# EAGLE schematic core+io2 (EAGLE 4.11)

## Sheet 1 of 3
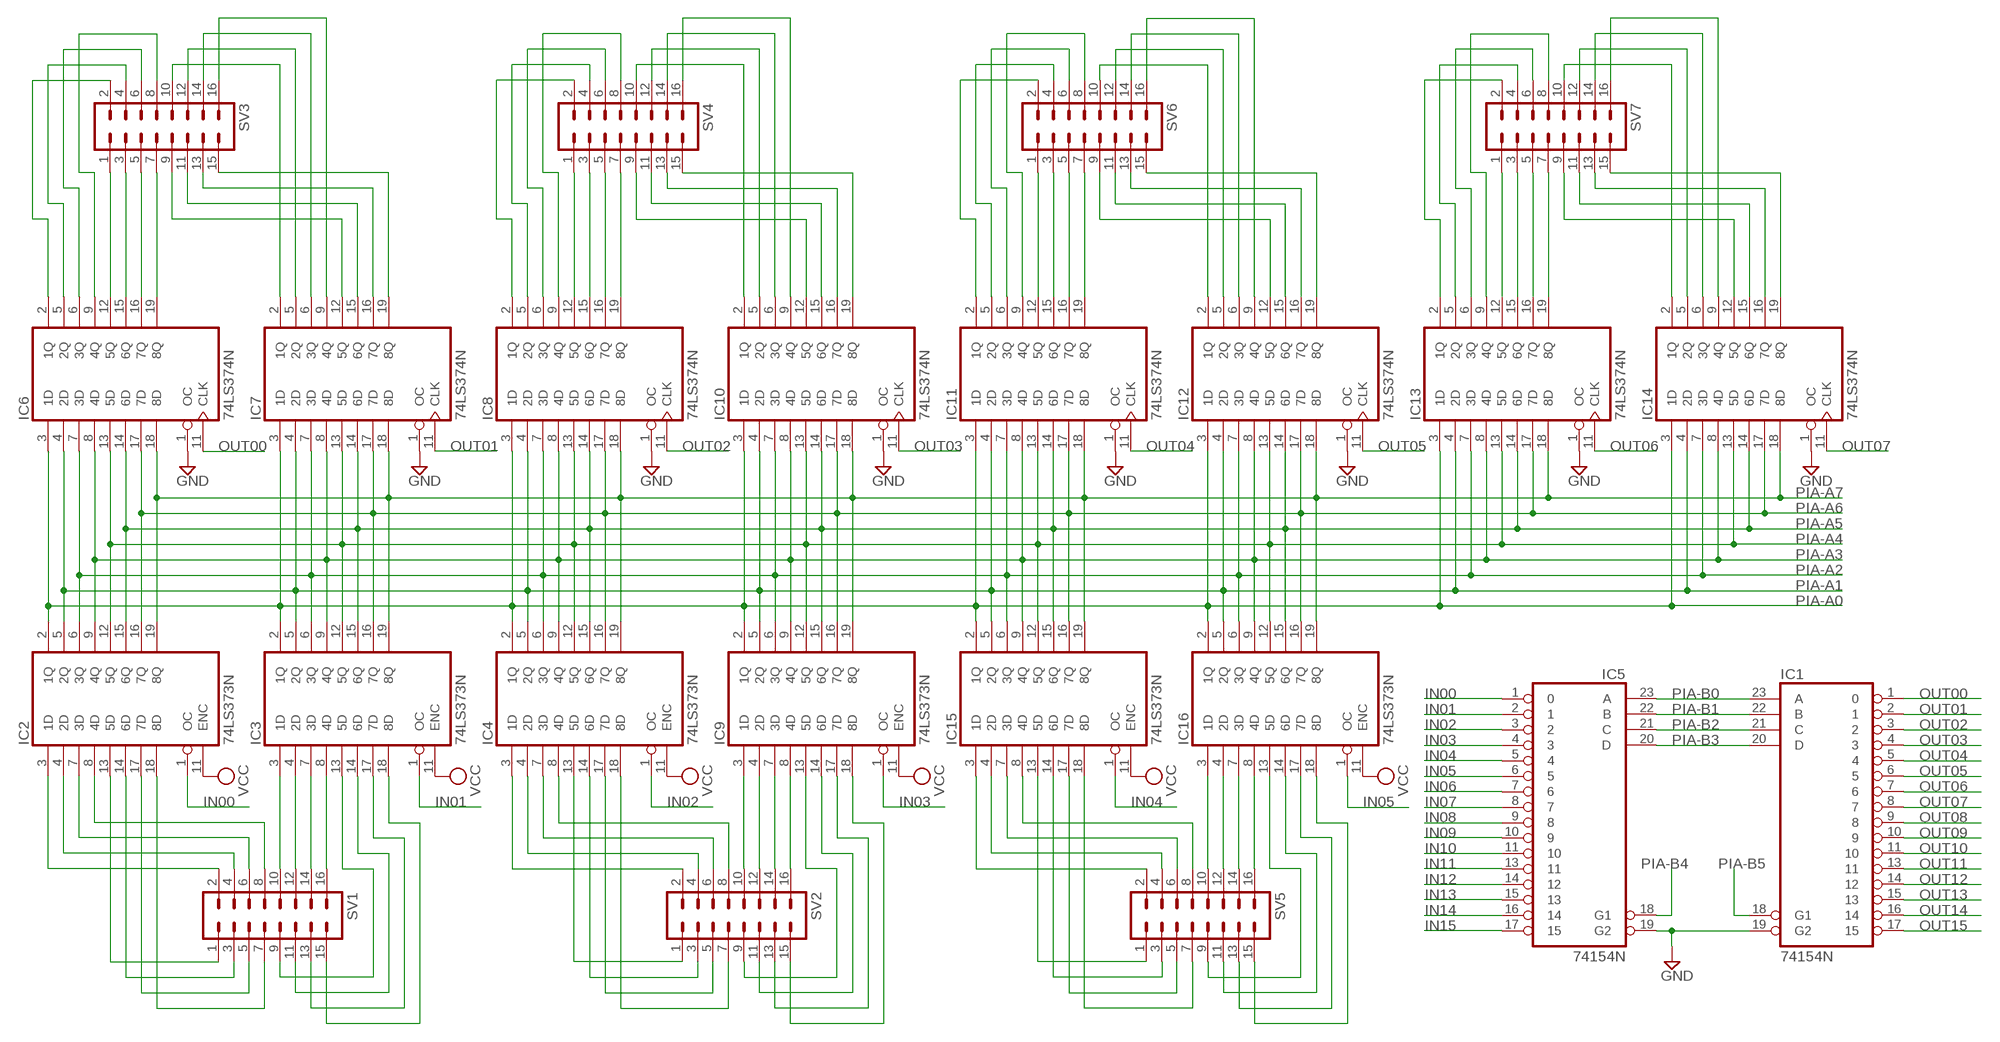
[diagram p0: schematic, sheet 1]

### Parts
IC1  74154N  [DIL24-6]
IC2  74LS373N  [DIL20]
IC3  74LS373N  [DIL20]
IC4  74LS373N  [DIL20]
IC5  74154N  [DIL24-6]
IC6  74LS374N  [DIL20]
IC7  74LS374N  [DIL20]
IC8  74LS374N  [DIL20]
IC9  74LS373N  [DIL20]
IC10  74LS374N  [DIL20]
IC11  74LS374N  [DIL20]
IC12  74LS374N  [DIL20]
IC13  74LS374N  [DIL20]
IC14  74LS374N  [DIL20]
IC15  74LS373N  [DIL20]
IC16  74LS373N  [DIL20]
SV1  MA08-2  [MA08-2]
SV2  MA08-2  [MA08-2]
SV3  MA08-2  [MA08-2]
SV4  MA08-2  [MA08-2]
SV5  MA08-2  [MA08-2]
SV6  MA08-2  [MA08-2]
SV7  MA08-2  [MA08-2]

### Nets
GND [Power]: IC1.19(G2) IC5.19(G2) IC6.1(OC) IC7.1(OC) IC8.1(OC) IC10.1(OC) IC11.1(OC) IC12.1(OC) IC13.1(OC) IC14.1(OC) ; also sheet 2,3
IN00: IC2.1(OC) IC5.1
IN01: IC3.1(OC) IC5.2
IN02: IC4.1(OC) IC5.3
IN03: IC5.4 IC9.1(OC)
IN04: IC5.5 IC15.1(OC)
IN05: IC5.6 IC16.1(OC)
IN06: IC5.7
IN07: IC5.8
IN08: IC5.9
IN09: IC5.10
IN10: IC5.11
IN11: IC5.13
IN12: IC5.14
IN13: IC5.15
IN14: IC5.16
IN15: IC5.17
N$1: IC3.3(1D) SV1.10
N$2: IC3.4(2D) SV1.12
N$7: IC3.7(3D) SV1.14
N$8: IC3.8(4D) SV1.16
N$9: IC2.8(4D) SV1.8
N$10: IC2.7(3D) SV1.6
N$11: IC2.4(2D) SV1.4
N$12: IC2.3(1D) SV1.2
N$13: IC2.13(5D) SV1.1
N$14: IC2.14(6D) SV1.3
N$15: IC2.17(7D) SV1.5
N$16: IC2.18(8D) SV1.7
N$17: IC3.13(5D) SV1.9
N$18: IC3.14(6D) SV1.11
N$19: IC3.17(7D) SV1.13
N$20: IC3.18(8D) SV1.15
N$26: IC11.2(1Q) IC13.2(1Q) SV6.2 SV7.2
N$29: IC9.3(1D) SV2.10
N$30: IC9.4(2D) SV2.12
N$31: IC9.7(3D) SV2.14
N$32: IC9.8(4D) SV2.16
N$33: IC8.12(5Q) SV4.1
N$34: IC8.15(6Q) SV4.3
N$35: IC8.16(7Q) SV4.5
N$36: IC8.19(8Q) SV4.7
N$37: IC4.3(1D) SV2.2
N$38: IC4.4(2D) SV2.4
N$39: IC4.7(3D) SV2.6
N$40: IC4.8(4D) SV2.8
N$41: IC9.13(5D) SV2.9
N$42: IC9.14(6D) SV2.11
N$43: IC9.17(7D) SV2.13
N$44: IC9.18(8D) SV2.15
N$45: IC4.13(5D) SV2.1
N$46: IC4.14(6D) SV2.3
N$47: IC4.17(7D) SV2.5
N$48: IC4.18(8D) SV2.7
N$49: IC8.5(2Q) SV4.4
N$50: IC8.6(3Q) SV4.6
N$51: IC8.2(1Q) SV4.2
N$52: IC8.9(4Q) SV4.8
N$53: IC6.12(5Q) SV3.1
N$54: IC6.15(6Q) SV3.3
N$55: IC6.16(7Q) SV3.5
N$56: IC6.19(8Q) SV3.7
N$57: IC6.2(1Q) SV3.2
N$58: IC6.5(2Q) SV3.4
N$59: IC6.6(3Q) SV3.6
N$60: IC6.9(4Q) SV3.8
N$61: IC7.19(8Q) SV3.15
N$62: IC7.16(7Q) SV3.13
N$63: IC7.15(6Q) SV3.11
N$64: IC7.12(5Q) SV3.9
N$65: IC7.2(1Q) SV3.10
N$66: IC7.5(2Q) SV3.12
N$67: IC7.6(3Q) SV3.14
N$68: IC7.9(4Q) SV3.16
N$69: IC10.2(1Q) SV4.10
N$70: IC10.5(2Q) SV4.12
N$71: IC10.6(3Q) SV4.14
N$72: IC10.9(4Q) SV4.16
N$73: IC10.19(8Q) SV4.15
N$74: IC10.16(7Q) SV4.13
N$75: IC10.15(6Q) SV4.11
N$76: IC10.12(5Q) SV4.9
N$77: IC16.3(1D) SV5.10
N$78: IC16.4(2D) SV5.12
N$79: IC16.7(3D) SV5.14
N$80: IC16.8(4D) SV5.16
N$81: IC11.12(5Q) SV6.1
N$82: IC11.15(6Q) SV6.3
N$83: IC11.16(7Q) SV6.5
N$84: IC11.19(8Q) SV6.7
N$85: IC13.12(5Q) SV7.1
N$86: IC13.15(6Q) SV7.3
N$87: IC13.16(7Q) SV7.5
N$88: IC13.19(8Q) SV7.7
N$89: IC11.5(2Q) SV6.4
N$90: IC11.6(3Q) SV6.6
N$91: IC11.9(4Q) SV6.8
N$92: IC12.12(5Q) SV6.9
N$93: IC12.15(6Q) SV6.11
N$95: IC12.16(7Q) SV6.13
N$96: IC12.19(8Q) SV6.15
N$97: IC12.2(1Q) SV6.10
N$98: IC12.5(2Q) SV6.12
N$99: IC12.6(3Q) SV6.14
N$100: IC12.9(4Q) SV6.16
N$101: IC15.3(1D) SV5.2
N$102: IC15.4(2D) SV5.4
N$103: IC15.7(3D) SV5.6
N$104: IC15.8(4D) SV5.8
N$105: IC16.13(5D) SV5.9
N$106: IC16.14(6D) SV5.11
N$107: IC16.17(7D) SV5.13
N$108: IC16.18(8D) SV5.15
N$109: IC15.13(5D) SV5.1
N$110: IC15.14(6D) SV5.3
N$111: IC15.17(7D) SV5.5
N$112: IC15.18(8D) SV5.7
N$113: IC14.19(8Q) SV7.15
N$114: IC14.16(7Q) SV7.13
N$115: IC14.15(6Q) SV7.11
N$116: IC14.12(5Q) SV7.9
N$117: IC14.2(1Q) SV7.10
N$118: IC14.5(2Q) SV7.12
N$119: IC14.6(3Q) SV7.14
N$120: IC14.9(4Q) SV7.16
N$121: IC13.9(4Q) SV7.8
N$122: IC13.6(3Q) SV7.6
N$123: IC13.5(2Q) SV7.4
OUT00: IC1.1 IC6.11(CLK)
OUT01: IC1.2 IC7.11(CLK)
OUT02: IC1.3 IC8.11(CLK)
OUT03: IC1.4 IC10.11(CLK)
OUT04: IC1.5 IC11.11(CLK)
OUT05: IC1.6 IC12.11(CLK)
OUT06: IC1.7 IC13.11(CLK)
OUT07: IC1.8 IC14.11(CLK)
OUT08: IC1.9
OUT09: IC1.10
OUT10: IC1.11
OUT11: IC1.13
OUT12: IC1.14
OUT13: IC1.15
OUT14: IC1.16
OUT15: IC1.17
PIA-A0: IC2.2(1Q) IC3.2(1Q) IC4.2(1Q) IC6.3(1D) IC7.3(1D) IC8.3(1D) IC9.2(1Q) IC10.3(1D) IC11.3(1D) IC12.3(1D) IC13.3(1D) IC14.3(1D) IC15.2(1Q) IC16.2(1Q) ; also sheet 2,3
PIA-A1: IC2.5(2Q) IC3.5(2Q) IC4.5(2Q) IC6.4(2D) IC7.4(2D) IC8.4(2D) IC9.5(2Q) IC10.4(2D) IC11.4(2D) IC12.4(2D) IC13.4(2D) IC14.4(2D) IC15.5(2Q) IC16.5(2Q) ; also sheet 2,3
PIA-A2: IC2.6(3Q) IC3.6(3Q) IC4.6(3Q) IC6.7(3D) IC7.7(3D) IC8.7(3D) IC9.6(3Q) IC10.7(3D) IC11.7(3D) IC12.7(3D) IC13.7(3D) IC14.7(3D) IC15.6(3Q) IC16.6(3Q) ; also sheet 2,3
PIA-A3: IC2.9(4Q) IC3.9(4Q) IC4.9(4Q) IC6.8(4D) IC7.8(4D) IC8.8(4D) IC9.9(4Q) IC10.8(4D) IC11.8(4D) IC12.8(4D) IC13.8(4D) IC14.8(4D) IC15.9(4Q) IC16.9(4Q) ; also sheet 2,3
PIA-A4: IC2.12(5Q) IC3.12(5Q) IC4.12(5Q) IC6.13(5D) IC7.13(5D) IC8.13(5D) IC9.12(5Q) IC10.13(5D) IC11.13(5D) IC12.13(5D) IC13.13(5D) IC14.13(5D) IC15.12(5Q) IC16.12(5Q) ; also sheet 2,3
PIA-A5: IC2.15(6Q) IC3.15(6Q) IC4.15(6Q) IC6.14(6D) IC7.14(6D) IC8.14(6D) IC9.15(6Q) IC10.14(6D) IC11.14(6D) IC12.14(6D) IC13.14(6D) IC14.14(6D) IC15.15(6Q) IC16.15(6Q) ; also sheet 2,3
PIA-A6: IC2.16(7Q) IC3.16(7Q) IC4.16(7Q) IC6.17(7D) IC7.17(7D) IC8.17(7D) IC9.16(7Q) IC10.17(7D) IC11.17(7D) IC12.17(7D) IC13.17(7D) IC14.17(7D) IC15.16(7Q) IC16.16(7Q) ; also sheet 2,3
PIA-A7: IC2.19(8Q) IC3.19(8Q) IC4.19(8Q) IC6.18(8D) IC7.18(8D) IC8.18(8D) IC9.19(8Q) IC10.18(8D) IC11.18(8D) IC12.18(8D) IC13.18(8D) IC14.18(8D) IC15.19(8Q) IC16.19(8Q) ; also sheet 2,3
PIA-B0: IC1.23(A) IC5.23(A) ; also sheet 2,3
PIA-B1: IC1.22(B) IC5.22(B) ; also sheet 2,3
PIA-B2: IC1.21(C) IC5.21(C) ; also sheet 2,3
PIA-B3: IC1.20(D) IC5.20(D) ; also sheet 2,3
PIA-B4: IC5.18(G1) ; also sheet 2,3
PIA-B5: IC1.18(G1) ; also sheet 2,3
VCC [Power]: IC2.11(ENC) IC3.11(ENC) IC4.11(ENC) IC9.11(ENC) IC15.11(ENC) IC16.11(ENC) ; also sheet 2,3

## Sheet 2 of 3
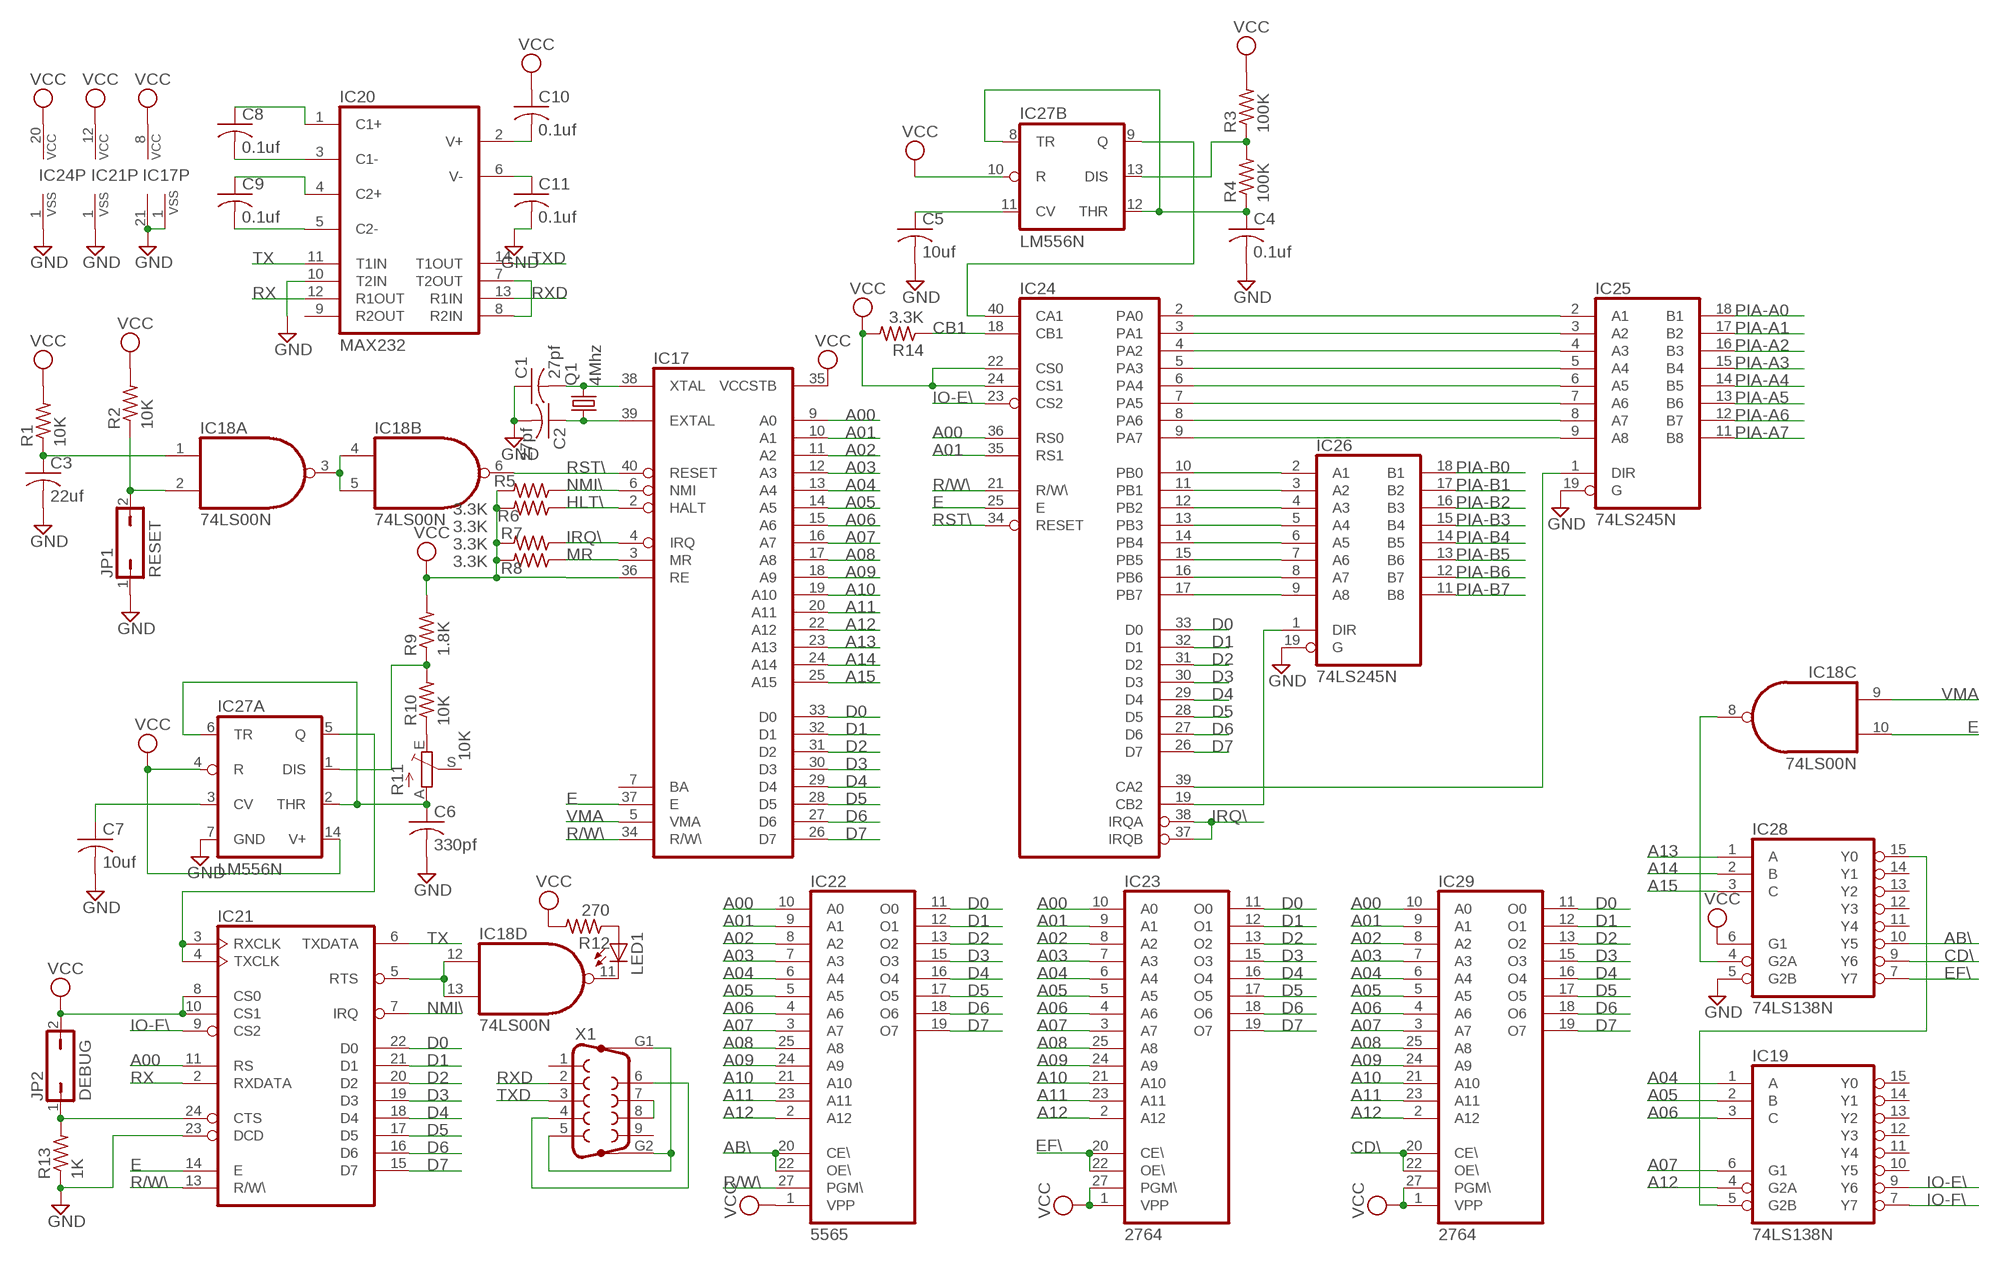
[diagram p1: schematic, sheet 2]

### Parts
C1  27pf  C-US050-025X075  [C050-025X075]
C2  27pf  C-US050-025X075  [C050-025X075]
C3  22uf  C-US050-025X075  [C050-025X075]
C4  0.1uf  C-US050-025X075  [C050-025X075]
C5  10uf  C-US050-025X075  [C050-025X075]
C6  330pf  C-US050-025X075  [C050-025X075]
C7  10uf  C-US050-025X075  [C050-025X075]
C8  0.1uf  C-US050-025X075  [C050-025X075]
C9  0.1uf  C-US050-025X075  [C050-025X075]
C10  0.1uf  C-US050-025X075  [C050-025X075]
C11  0.1uf  C-US050-025X075  [C050-025X075]
IC17  6802  [DIL40]
IC18  74LS00N  [DIL14]
IC19  74LS138N  [DIL16]
IC20  MAX232  [DIL16]
IC21  6850  [DIL24]
IC22  5565  2764  [DIL28]
IC23  2764  [DIL28]
IC24  6821  [DIL40]
IC25  74LS245N  [DIL20]
IC26  74LS245N  [DIL20]
IC27  LM556N  [DIL14]
IC28  74LS138N  [DIL16]
IC29  2764  [DIL28]
JP1  RESET  JP1Q  [JP1]
JP2  DEBUG  JP1Q  [JP1]
LED1  LED3MM  [LED3MM]
Q1  4Mhz  CRYTALHC18U-V  [HC18U-V]
R1  10K  R-US_0207/7  [0207/7]
R2  10K  R-US_0207/7  [0207/7]
R3  100K  R-US_0207/7  [0207/7]
R4  100K  R-US_0207/7  [0207/7]
R5  3.3K  R-US_0207/7  [0207/7]
R6  3.3K  R-US_0207/7  [0207/7]
R7  3.3K  R-US_0207/7  [0207/7]
R8  3.3K  R-US_0207/7  [0207/7]
R9  1.8K  R-US_0207/7  [0207/7]
R10  10K  R-US_0207/7  [0207/7]
R11  10K  TRIM_EU-B90P  [SP19L]
R12  270  R-US_0207/7  [0207/7]
R13  1K  R-US_0207/7  [0207/7]
R14  3.3K  R-US_0207/7  [0207/7]
X1  F09HP  [F09HP]

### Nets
A00: IC17.9(A0) IC21.11(RS) IC22.10(A0) IC23.10(A0) IC24.36(RS0) IC29.10(A0)
A01: IC17.10(A1) IC22.9(A1) IC23.9(A1) IC24.35(RS1) IC29.9(A1)
A02: IC17.11(A2) IC22.8(A2) IC23.8(A2) IC29.8(A2)
A03: IC17.12(A3) IC22.7(A3) IC23.7(A3) IC29.7(A3)
A04: IC17.13(A4) IC19.1(A) IC22.6(A4) IC23.6(A4) IC29.6(A4)
A05: IC17.14(A5) IC19.2(B) IC22.5(A5) IC23.5(A5) IC29.5(A5)
A06: IC17.15(A6) IC19.3(C) IC22.4(A6) IC23.4(A6) IC29.4(A6)
A07: IC17.16(A7) IC19.6(G1) IC22.3(A7) IC23.3(A7) IC29.3(A7)
A08: IC17.17(A8) IC22.25(A8) IC23.25(A8) IC29.25(A8)
A09: IC17.18(A9) IC22.24(A9) IC23.24(A9) IC29.24(A9)
A10: IC17.19(A10) IC22.21(A10) IC23.21(A10) IC29.21(A10)
A11: IC17.20(A11) IC22.23(A11) IC23.23(A11) IC29.23(A11)
A12: IC17.22(A12) IC19.4(G2A) IC22.2(A12) IC23.2(A12) IC29.2(A12)
A13: IC17.23(A13) IC28.1(A)
A14: IC17.24(A14) IC28.2(B)
A15: IC17.25(A15) IC28.3(C)
AB\: IC22.20(CE\) IC22.22(OE\) IC28.10(Y5)
CB1: IC24.18(CB1) R14.1
CD\: IC28.9(Y6) IC29.20(CE\) IC29.22(OE\)
D0: IC17.33(D0) IC21.22(D0) IC22.11(O0) IC23.11(O0) IC24.33(D0) IC29.11(O0)
D1: IC17.32(D1) IC21.21(D1) IC22.12(O1) IC23.12(O1) IC24.32(D1) IC29.12(O1)
D2: IC17.31(D2) IC21.20(D2) IC22.13(O2) IC23.13(O2) IC24.31(D2) IC29.13(O2)
D3: IC17.30(D3) IC21.19(D3) IC22.15(O3) IC23.15(O3) IC24.30(D3) IC29.15(O3)
D4: IC17.29(D4) IC21.18(D4) IC22.16(O4) IC23.16(O4) IC24.29(D4) IC29.16(O4)
D5: IC17.28(D5) IC21.17(D5) IC22.17(O5) IC23.17(O5) IC24.28(D5) IC29.17(O5)
D6: IC17.27(D6) IC21.16(D6) IC22.18(O6) IC23.18(O6) IC24.27(D6) IC29.18(O6)
D7: IC17.26(D7) IC21.15(D7) IC22.19(O7) IC23.19(O7) IC24.26(D7) IC29.19(O7)
E: IC17.37(E) IC18.10(C:I1) IC21.14(E) IC24.25(E)
EF\: IC23.20(CE\) IC23.22(OE\) IC28.7(Y7)
GND [Power]: C1.1 C2.2 C3.2 C4.2 C5.2 C6.2 C7.2 C11.2 IC17.1(VSS) IC17.21(VSS) IC20.10(T2IN) IC21.1(VSS) IC21.23(DCD) IC24.1(VSS) IC25.19(G) IC26.19(G) IC27.7(A:GND) IC28.5(G2B) JP1.1 R13.1 ; also sheet 1,3
HLT\: IC17.2(HALT) R5.1
IO-E\: IC19.9(Y6) IC24.23(CS2)
IO-F\: IC19.7(Y7) IC21.9(CS2)
IRQ\: IC17.4(IRQ) IC24.37(IRQB) IC24.38(IRQA) R7.1
MR: IC17.3(MR) R8.1
N$3: C2.1 IC17.39(EXTAL) Q1.1
N$4: C1.2 IC17.38(XTAL) Q1.2
N$5: IC24.2(PA0) IC25.2(A1)
N$6: IC18.3(A:O) IC18.4(B:I0) IC18.5(B:I1)
N$21: C3.1 IC18.1(A:I0) R1.1
N$22: IC18.2(A:I1) JP1.2 R2.1
N$23: IC21.3(RXCLK) IC21.4(TXCLK) IC27.5(A:Q)
N$24: IC24.10(PB0) IC26.2(A1)
N$25: IC24.11(PB1) IC26.3(A2)
N$27: C6.1 IC27.2(A:THR) IC27.6(A:TR) R11.A
N$28: IC27.1(A:DIS) R9.1 R10.2
N$94: IC24.12(PB2) IC26.4(A3)
N$124: IC24.13(PB3) IC26.5(A4)
N$125: IC24.14(PB4) IC26.6(A5)
N$126: IC24.15(PB5) IC26.7(A6)
N$127: IC24.16(PB6) IC26.8(A7)
N$128: IC24.17(PB7) IC26.9(A8)
N$129: IC24.3(PA1) IC25.3(A2)
N$130: IC24.4(PA2) IC25.4(A3)
N$131: IC24.5(PA3) IC25.5(A4)
N$132: IC24.6(PA4) IC25.6(A5)
N$133: IC24.7(PA5) IC25.7(A6)
N$134: IC24.8(PA6) IC25.8(A7)
N$135: IC24.9(PA7) IC25.9(A8)
N$136: IC24.19(CB2) IC26.1(DIR)
N$137: IC24.39(CA2) IC25.1(DIR)
N$138: IC24.40(CA1) IC27.9(B:Q)
N$140: C4.1 IC27.8(B:TR) IC27.12(B:THR) R4.1
N$141: IC27.13(B:DIS) R3.1 R4.2
N$142: C5.1 IC27.11(B:CV)
N$143: R10.1 R11.E
N$144: X1.4 X1.6
N$145: X1.7 X1.8
N$146: X1.5 X1.G1 X1.G2
N$147: IC18.12(D:I0) IC18.13(D:I1) IC21.5(RTS)
N$148: IC18.11(D:O) LED1.K(C)
N$149: LED1.A R12.1
N$150: IC21.24(CTS) JP2.1 R13.2
N$151: IC18.8(C:O) IC28.4(G2A)
N$152: IC19.5(G2B) IC28.15(Y0)
N$153: IC20.7(T2OUT) IC20.8(R2IN)
N$154: C7.1 IC27.3(A:CV)
N$155: C9.2 IC20.5(C2-)
N$156: C9.1 IC20.4(C2+)
N$157: C8.2 IC20.3(C1-)
N$158: C8.1 IC20.1(C1+)
N$159: C11.1 IC20.6(V-)
N$160: C10.2 IC20.2(V+)
NMI\: IC17.6(NMI) IC21.7(IRQ) R6.1
PIA-A0: IC25.18(B1) ; also sheet 1,3
PIA-A1: IC25.17(B2) ; also sheet 1,3
PIA-A2: IC25.16(B3) ; also sheet 1,3
PIA-A3: IC25.15(B4) ; also sheet 1,3
PIA-A4: IC25.14(B5) ; also sheet 1,3
PIA-A5: IC25.13(B6) ; also sheet 1,3
PIA-A6: IC25.12(B7) ; also sheet 1,3
PIA-A7: IC25.11(B8) ; also sheet 1,3
PIA-B0: IC26.18(B1) ; also sheet 1,3
PIA-B1: IC26.17(B2) ; also sheet 1,3
PIA-B2: IC26.16(B3) ; also sheet 1,3
PIA-B3: IC26.15(B4) ; also sheet 1,3
PIA-B4: IC26.14(B5) ; also sheet 1,3
PIA-B5: IC26.13(B6) ; also sheet 1,3
PIA-B6: IC26.12(B7) ; also sheet 3
PIA-B7: IC26.11(B8) ; also sheet 3
R/W\: IC17.34(R/W\) IC21.13(R/W\) IC22.27(PGM\) IC24.21(R/W\)
RST\: IC17.40(RESET) IC18.6(B:O) IC24.34(RESET)
RX: IC20.12(R1OUT) IC21.2(RXDATA)
RXD: IC20.13(R1IN) X1.2
TX: IC20.11(T1IN) IC21.6(TXDATA)
TXD: IC20.14(T1OUT) X1.3
VCC [Power]: C10.1 IC17.8(VCC) IC17.35(VCCSTB) IC17.36(RE) IC21.8(CS0) IC21.10(CS1) IC21.12(VCC) IC22.1(VPP) IC23.1(VPP) IC23.27(PGM\) IC24.20(VCC) IC24.22(CS0) IC24.24(CS1) IC27.4(A:R) IC27.10(B:R) IC27.14(A:V+) IC28.6(G1) IC29.1(VPP) IC29.27(PGM\) JP2.2 R1.2 R2.2 R3.2 R5.2 R6.2 R7.2 R8.2 R9.2 R12.2 R14.2 ; also sheet 1,3
VMA: IC17.5(VMA) IC18.9(C:I0)
Unconnected: IC17.7(BA) IC19.10(Y5) IC19.11(Y4) IC19.12(Y3) IC19.13(Y2) IC19.14(Y1) IC19.15(Y0) IC20.9(R2OUT) IC28.11(Y4) IC28.12(Y3) IC28.13(Y2) IC28.14(Y1) R11.S X1.1 X1.9

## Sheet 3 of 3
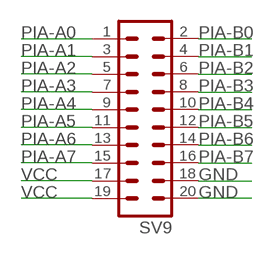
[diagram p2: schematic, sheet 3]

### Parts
SV9  MA10-2  [MA10-2]

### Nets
GND [Power]: SV9.18 SV9.20 ; also sheet 1,2
PIA-A0: SV9.1 ; also sheet 1,2
PIA-A1: SV9.3 ; also sheet 1,2
PIA-A2: SV9.5 ; also sheet 1,2
PIA-A3: SV9.7 ; also sheet 1,2
PIA-A4: SV9.9 ; also sheet 1,2
PIA-A5: SV9.11 ; also sheet 1,2
PIA-A6: SV9.13 ; also sheet 1,2
PIA-A7: SV9.15 ; also sheet 1,2
PIA-B0: SV9.2 ; also sheet 1,2
PIA-B1: SV9.4 ; also sheet 1,2
PIA-B2: SV9.6 ; also sheet 1,2
PIA-B3: SV9.8 ; also sheet 1,2
PIA-B4: SV9.10 ; also sheet 1,2
PIA-B5: SV9.12 ; also sheet 1,2
PIA-B6: SV9.14 ; also sheet 2
PIA-B7: SV9.16 ; also sheet 2
VCC [Power]: SV9.17 SV9.19 ; also sheet 1,2

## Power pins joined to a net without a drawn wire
GND: IC1.12(GND) IC2.10(GND) IC3.10(GND) IC4.10(GND) IC5.12(GND) IC6.10(GND) IC7.10(GND) IC8.10(GND) IC9.10(GND) IC10.10(GND) IC11.10(GND) IC12.10(GND) IC13.10(GND) IC14.10(GND) IC15.10(GND) IC16.10(GND) IC18.7(P:GND) IC19.8(GND) IC20.15(GND) IC22.14(GND) IC23.14(GND) IC25.10(GND) IC26.10(GND) IC28.8(GND) IC29.14(GND)
VCC: IC1.24(VCC) IC2.20(VCC) IC3.20(VCC) IC4.20(VCC) IC5.24(VCC) IC6.20(VCC) IC7.20(VCC) IC8.20(VCC) IC9.20(VCC) IC10.20(VCC) IC11.20(VCC) IC12.20(VCC) IC13.20(VCC) IC14.20(VCC) IC15.20(VCC) IC16.20(VCC) IC18.14(P:VCC) IC19.16(VCC) IC20.16(VCC) IC22.28(VCC) IC23.28(VCC) IC25.20(VCC) IC26.20(VCC) IC28.16(VCC) IC29.28(VCC)

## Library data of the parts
C1-C11 = rcl:C-US: CAPACITOR, American symbol
IC1 IC5 = 74xx-us:74*154: 4-line to 16-line data SELECTOR/MULTIPLEXER
IC2-IC4 IC9 IC15 IC16 = 74xx-us:74*373: Octal D type transparent LATCH, edge triggered
IC6-IC8 IC10-IC14 = 74xx-us:74*374: Octal D type transparent LATCH, edge triggered
IC17 = micro-motorola:6802: MICROCONTROLLER/MEMORY DEVICE
IC18 = 74xx-us:74*00: Quad 2-input NAND gate
IC19 IC28 = 74xx-us:74*138: 3-line to 8-line DECODER/DEMULTIPLEXER
IC20 = maxim:MAX232: RS232 TRANSEIVER
IC21 = micro-motorola:6850: MICROCONTROLLER/MEMORY DEVICE
IC22 IC23 IC29 = memory:2764: MEMORY
IC24 = micro-motorola:6821: MICROCONTROLLER/MEMORY DEVICE
IC25 IC26 = 74xx-us:74*245: Octal BUS TRANSCEIVER, 3-state
IC27 = linear:*556: Dual TIMER
JP1 JP2 = jumper:JP1Q: JUMPER
LED1 = led:LED: LED
Q1 = crystal:CRYTAL: CRYSTAL
R1-R10 R12-R14 = rcl:R-US_: RESISTOR, American symbol
R11 = pot:TRIM_EU-: POTENTIOMETER
SV1-SV7 = con-lstb:MA08-2: PIN HEADER
SV9 = con-lstb:MA10-2: PIN HEADER
X1 = con-subd:F09HP: SUB-D

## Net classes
1 Power: width 0.508 mm, drill 0.254 mm, clearance 0.254 mm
